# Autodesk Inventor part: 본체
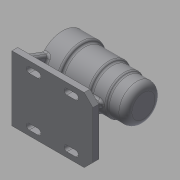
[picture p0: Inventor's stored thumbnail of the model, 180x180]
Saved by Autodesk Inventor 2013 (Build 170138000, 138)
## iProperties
Created: 2017-09
Part Number: 본체
Material: 일반
Document SubType Name: Modeling
Designer: Windows7
Density: 1 g/cm^3
Author: Windows7
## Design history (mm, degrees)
sketch "스케치1"
  geometry: L1 (-56, 0)-(56, 0); L2 (56, 21)-(41, 21); L3 (41, 21)-(41, 24); L4 (41, 24)-(-13, 24); L5 (-13, 24)-(-13, 21); L6 (-13, 21)-(-25, 21); L7 (-25, 21)-(-25, 17.5); L8 (-25, 17.5)-(-43, 17.5); L9 (-43, 17.5)-(-43, 16); L10 (-43, 16)-(-47, 16); L11 (-47, 16)-(-47, 10.5); L12 (-47, 10.5)-(-50, 10.5); L13 (-50, 10.5)-(-50, 0); L14 (56, 21)-(56, 34); L15 (56, 34)-(28, 34); L16 (28, 34)-(28, 30); L17 (28, 30)-(-8, 30); L18 (-11, 27)-(-11, 27); L19 (-13.196, 27)-(-31, 27); L20 (-31, 27)-(-31, 25); L21 (-31, 25)-(-47, 25); L22 (-56, 16)-(-56, 0); A1 r 9 centre (-47, 16) between (-47, 25) and (-56, 16); A2 r 3 centre (-8, 27) between (-8, 30) and (-10.598, 28.5); A3 r 3 centre (-13.196, 30) between (-13.196, 27) and (-10.598, 28.5); 4 further points
  constraints: 44 end point, 12 parallel, 7 point on circle, 7 tangent, 6 perpendicular, 6 point on line, 3 centre point, 1 coincident, 1 collinear, 1 equal radius, 1 horizontal, 1 horizontal alignment, 1 midpoint
  dimensions: "d0" = 112 distance of L1.start L1.end; "d2" = 21 distance of L1.end L2.start; "d3" = 15 distance of L2.start L2.end; "d4" = 3 distance of L2.end L3.end; "d5" = 54 distance of L3.end L4.end; "d6" = 3 distance of L4.end L5.end; "d7" = 12 distance of L5.end L6.end; "d8" = 3.5 distance of L6.end L7.end; "d9" = 18 distance of L7.end L8.end; "d10" = 1.5 distance of L8.end L9.end; "d11" = 4 distance of L9.end L10.end; "d12" = 5.5 distance of L10.end L11.end; "d13" = 3 distance of L11.end L12.end; "d14" = 10.5 distance of L12.end L13.end; "d15" = 13 distance of L2.start L14.end; "d16" = 28 distance of L14.end L15.end; "d17" = 4 distance of L15.end L16.end; "d18" = 39 distance of L16.end point (-11, 30); "d19" = 3 distance of point (-11, 30) L18.end; "d20" = 20 distance of L18.end L19.end; "d21" = 2 distance of L19.end L20.end; "d22" = 25 distance of L20.end point (-56, 25); "d23" = 9 radius of A1; "d24" = 3 radius of A2
revolve "회전1" sketch "스케치1" stored, may be unused: angle "d25" = 90 deg
node "작업 평면1"
sketch "스케치2"
  geometry: L1 (-56, 45)-(56, 45); L2 (56, 45)-(56, -45); L3 (56, -45)-(-56, -45); L4 (-56, -45)-(-56, 45); 3 further points
  constraints: 8 end point, 2 midpoint, 2 parallel, 1 horizontal, 1 horizontal alignment, 1 perpendicular, 1 vertical alignment
  dimensions: "d27" = 112 distance of L1.start L1.end; "d29" = 90 distance of L1.end L2.end
extrude "돌출1" join sketch "스케치2" distance "d30" = 8; taper "d31" = 0 deg
sketch "스케치3"
  geometry: L1 (10, 8)-(23.1, 43.992); L2 (80, 8)-(66.9, 43.992); L3 (10, 8)-(80, 8); A1 r 34 centre (45, 70) between (23.1, 43.992) and (66.9, 43.992); 1 further point
  constraints: 6 end point, 2 point on circle, 1 centre point, 1 coincident, 1 horizontal
  dimensions: "d37" = 68 diameter of A1; "d38" = 70 deg angle of L2 L3; "d39" = 40 deg angle of L2 L1; "d41" = 11.68399 distance from line of point (45, 70) L2; "d42" = 62 distance from line of point (45, 70) L3; "d43" = 11.68399 distance from line of point (45, 70) L1
extrude "돌출2" join sketch "스케치3" distance "d44" = 8; taper "d45" = 0 deg
sketch "스케치4"
  geometry: L1 (34, -62)-(23.885, -24.25); L2 (34, -62)-(56, -62); L3 (56, -70)-(56, -62) reference; 1 further point
  constraints: 4 end point, 1 perpendicular
  dimensions: "d48" = 16.7947 distance from line of point (0, 0) L1; "d49" = 70.71068 distance of point (0, 0) L1.start; "d50" = 34.03739 distance of point (0, 0) L1.end
feature "리브1" sketch "스케치4" dims "d51" = 1, "d52" = 8, "d53" = 0, "d54" = 0, "d55" = 1, "d56" = 1
sketch "스케치5"
  geometry: L1 (34, -4)-(-48, -4) reference; L2 (56, -45)-(56, 45) reference; L3 (56, 45)-(-56, 45) reference; L4 (-48, 4)-(34, 4) reference; L5 (-56, -45)-(-56, 45) reference; L6 (-20, 30)-(-32, 30); L7 (-20, 38)-(-32, 38); L8 (32, 30)-(20, 30); L9 (32, 38)-(20, 38); L10 (32, -30)-(20, -30); L11 (32, -38)-(20, -38); L12 (-20, -30)-(-32, -30); L13 (-20, -38)-(-32, -38); A1 r 4 centre (-32, 34) between (-32, 38) and (-32, 30); A2 r 4 centre (-20, 34) between (-20, 30) and (-20, 38); A3 r 4 centre (20, 34) between (20, 38) and (20, 30); A4 r 4 centre (32, 34) between (32, 30) and (32, 38); A5 r 4 centre (20, -34) between (20, -30) and (20, -38); A6 r 4 centre (32, -34) between (32, -38) and (32, -30); A7 r 4 centre (-32, -34) between (-32, -30) and (-32, -38); A8 r 4 centre (-20, -34) between (-20, -38) and (-20, -30); 1 further point
  constraints: 18 tangent, 16 end point, 16 point on circle, 8 centre point, 3 parallel, 1 equal radius
  dimensions: "d59" = 8 diameter of A1; "d61" = 8 diameter of A2; "d63" = 8 diameter of A3; "d65" = 8 diameter of A4; "d66" = 90 deg angle of L2 L12; "d67" = 90 deg angle of L2 L13; "d68" = 15 distance between parallel lines of L3 L8; "d69" = 75 distance between parallel lines of L3 L10; "d70" = 75 distance from line of L2.end L12; "d71" = 83 distance from line of L2.end L13; "d72" = 24 distance from line of L9.start L2; "d73" = 42 distance from line of L9.start L1; "d74" = 24 distance from line of L10.start L2; "d75" = 36 distance from line of L10.end L2; "d76" = 76 distance from line of L7.start L2; "d77" = 42 distance from line of L7.start L1; "d78" = 76 distance from line of L12.start L2; "d79" = 88 distance from line of L12.end L2
extrude "돌출3" cut sketch "스케치5" distance "d80" = 8; taper "d81" = 0 deg
sketch "스케치6"
  geometry: L1 (90, 0)-(0, 0) reference; L2 (90, 0)-(90, 8) reference; 3 further points
  dimensions: "d86" = 57 distance from line of point (67.517, 57) L1; "d87" = 22.48334 distance from line of point (67.517, 57) L2; "d88" = 96 distance from line of point (45, 96) L1; "d89" = 45 distance from line of point (45, 96) L2; "d90" = 57 distance from line of point (22.483, 57) L1; "d91" = 67.51666 distance from line of point (22.483, 57) L2
hole "구멍1" sketch "스케치6" at (22.483, 57), (67.517, 57), (45, 96) diameter "d92" = 3.242; stored, may be unused: countersink angle "d96" = 90 deg, drill point angle "d98" = 118 deg; dims "d93" = 8, "d94" = 4, "d95" = 2, "d97" = 11
sketch "스케치7"
  geometry: L1 (112, 0)-(0, 0) reference; L2 (112, 0)-(112, 8) reference; 2 further points
  constraints: 1 other
  dimensions: "d101" = 70 distance from line of point (64, 70) L1; "d102" = 48 distance from line of point (64, 70) L2
feature "엠보싱1" sketch "스케치7" dims "d0" = 112, "d2" = 21, "d3" = 15, "d4" = 3, "d5" = 54, "d6" = 3, "d7" = 12, "d8" = 3.5, "d9" = 18, "d10" = 1.5, "d11" = 4, "d12" = 5.5, "d13" = 3, "d14" = 10.5, "d15" = 13, "d16" = 28, "d17" = 4, "d18" = 39, "d19" = 3, "d20" = 20, "d21" = 2, "d22" = 25, "d23" = 9, "d24" = 3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
chamfer "모따기1" distance "d105" = 12; stored, may be unused: second distance "d106" = 2, angle "d107" = 45 deg
chamfer "모따기2" distance "d108" = 1; stored, may be unused: second distance "d109" = 2, angle "d110" = 45 deg
fillet "모깎기1" dims "d111" = 3
fillet "모깎기2" dims "d112" = 0.3
fillet "모깎기3" dims "d113" = 3, "d114" = 2
fillet "모깎기4" dims "d115" = 3
node "솔리드1"
